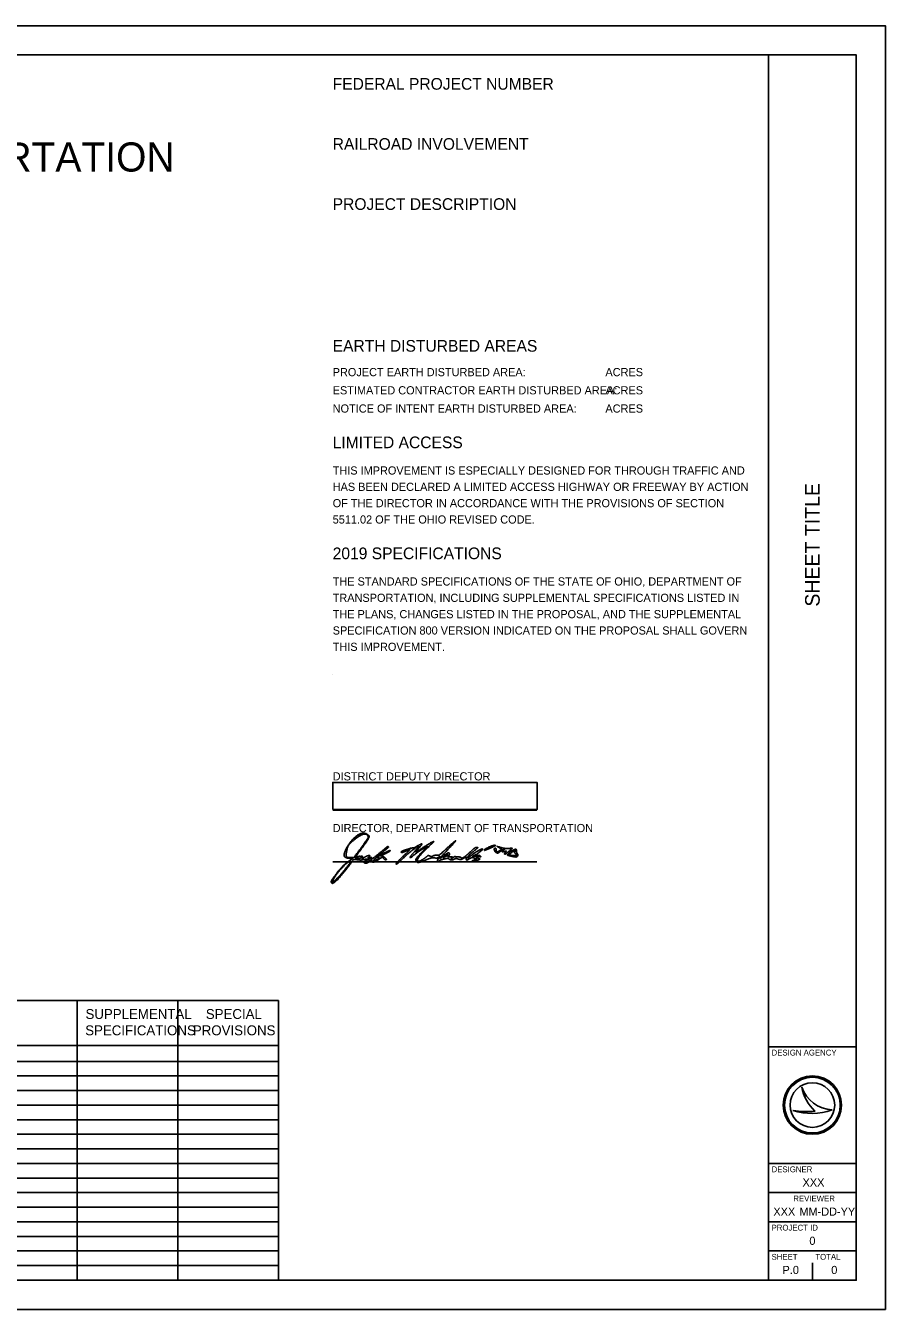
# Model space of a CAD drawing. Extents: x -15 to 405, y -40 to 87.
# Drawn here: x 71.42 to 86.16, y -40.29 to -18.29 of the extents above; entities that cross this region are included whole.
import ezdxf

# ---------------------------------------------------------------- set-up
doc = ezdxf.new("R2010")
doc.units = 0
for name, color, linetype in [('GM_X_Adjacent_County', 7, 'Continuous'), ('GM_X_County', 7, 'Continuous'), ('GM_X_Section', 7, 'Continuous'), ('GM_X_Township', 7, 'Continuous')]:
    doc.layers.add(name, color=color, linetype=linetype)

msp = doc.modelspace()

# ---------------------------------------------------------------- linework, layer by layer
at = {"layer": 'GM_X_Adjacent_County'}
for p, q in [((77.146, -32.413), (77.146, -32.413)), ((77.466, -32.544), (77.466, -32.544)), ((77.511, -32.502), (77.511, -32.502)), ((77.883, -32.531), (77.883, -32.531)), ((78.66, -32.5), (78.66, -32.5)), ((79.285, -32.413), (79.285, -32.413)), ((79.738, -32.52), (79.738, -32.52))]:
    msp.add_line(p, q, dxfattribs=at)
for points in [[(76.998, -32.58), (77.029, -32.558), (76.991, -32.558)], [(78.608, -32.52), (78.579, -32.546), (78.62, -32.526)], [(79.549, -32.423), (79.585, -32.401), (79.545, -32.379)], [(79.798, -32.507), (79.854, -32.506), (79.825, -32.484)], [(77.241, -32.599), (77.262, -32.567), (77.221, -32.577)]]:
    msp.add_lwpolyline(points, dxfattribs=at)
for points in [[(77.038, -32.251), (76.972, -32.308), (76.933, -32.372), (76.922, -32.443)], [(76.935, -32.362), (77.021, -32.211), (77.229, -32.095), (77.295, -32.161)], [(77.286, -32.17), (77.26, -32.128), (77.134, -32.169), (77.038, -32.251)], [(77.146, -32.413), (77.267, -32.249), (77.3, -32.193), (77.286, -32.17)], [(77.295, -32.223), (77.284, -32.246), (77.232, -32.322), (77.18, -32.391)], [(77.295, -32.161), (77.313, -32.18), (77.313, -32.185), (77.295, -32.223)], [(78.129, -32.35), (78.208, -32.304), (78.22, -32.317), (78.161, -32.384)], [(78.188, -32.403), (78.269, -32.347), (78.4, -32.269), (78.416, -32.269)], [(78.416, -32.269), (78.421, -32.269), (78.379, -32.312), (78.324, -32.364)], [(78.643, -32.383), (78.718, -32.314), (78.784, -32.257), (78.789, -32.257)], [(78.789, -32.257), (78.795, -32.257), (78.743, -32.317), (78.674, -32.391)], [(79.285, -32.413), (79.285, -32.401), (79.438, -32.331), (79.457, -32.334)], [(79.457, -32.334), (79.478, -32.338), (79.478, -32.338), (79.357, -32.393)], [(76.991, -32.558), (76.893, -32.556), (76.87, -32.475), (76.935, -32.362)], [(76.922, -32.443), (76.91, -32.517), (76.932, -32.544), (77, -32.544)], [(77, -32.544), (77.046, -32.544), (77.051, -32.54), (77.146, -32.413)], [(77.091, -32.545), (77.069, -32.546), (77.069, -32.547), (77.096, -32.558)], [(77.18, -32.391), (77.128, -32.461), (77.085, -32.521), (77.085, -32.526)], [(77.085, -32.526), (77.085, -32.531), (77.101, -32.531), (77.12, -32.527)], [(77.135, -32.531), (77.125, -32.538), (77.105, -32.545), (77.091, -32.545)], [(77.096, -32.558), (77.126, -32.57), (77.182, -32.545), (77.164, -32.528)], [(77.12, -32.527), (77.145, -32.521), (77.149, -32.522), (77.135, -32.531)], [(77.164, -32.528), (77.16, -32.523), (77.166, -32.519), (77.178, -32.519)], [(77.178, -32.519), (77.193, -32.519), (77.198, -32.526), (77.193, -32.538)], [(77.193, -32.538), (77.184, -32.561), (77.197, -32.562), (77.229, -32.54)], [(77.229, -32.54), (77.258, -32.52), (77.323, -32.503), (77.323, -32.515)], [(77.263, -32.619), (77.286, -32.619), (77.412, -32.531), (77.525, -32.435)], [(77.301, -32.539), (77.282, -32.553), (77.284, -32.554), (77.317, -32.549)], [(77.323, -32.515), (77.323, -32.519), (77.313, -32.53), (77.301, -32.539)], [(77.317, -32.549), (77.353, -32.543), (77.353, -32.544), (77.308, -32.569)], [(77.466, -32.544), (77.449, -32.538), (77.433, -32.543), (77.413, -32.561)], [(77.541, -32.449), (77.448, -32.523), (77.427, -32.544), (77.471, -32.521)], [(77.438, -32.58), (77.485, -32.557), (77.488, -32.552), (77.466, -32.544)], [(77.471, -32.521), (77.483, -32.514), (77.507, -32.512), (77.524, -32.516)], [(77.557, -32.557), (77.54, -32.533), (77.538, -32.534), (77.472, -32.576)], [(77.515, -32.507), (77.51, -32.507), (77.508, -32.505), (77.511, -32.502)], [(77.511, -32.502), (77.532, -32.485), (77.664, -32.419), (77.669, -32.424)], [(77.669, -32.424), (77.675, -32.43), (77.532, -32.507), (77.515, -32.507)], [(77.524, -32.516), (77.56, -32.525), (77.618, -32.582), (77.592, -32.582)], [(77.525, -32.435), (77.575, -32.392), (77.621, -32.357), (77.626, -32.357)], [(77.626, -32.357), (77.651, -32.357), (77.627, -32.382), (77.541, -32.449)], [(77.592, -32.582), (77.582, -32.582), (77.566, -32.571), (77.557, -32.557)], [(77.773, -32.656), (77.762, -32.656), (77.812, -32.6), (77.883, -32.531)], [(78.157, -32.35), (78.148, -32.34), (77.938, -32.507), (77.86, -32.587)], [(77.86, -32.448), (77.861, -32.437), (78.048, -32.374), (78.064, -32.379)], [(77.941, -32.432), (77.879, -32.459), (77.86, -32.462), (77.86, -32.448)], [(77.883, -32.531), (77.954, -32.463), (78.009, -32.407), (78.006, -32.407)], [(78.006, -32.407), (78.003, -32.407), (77.974, -32.418), (77.941, -32.432)], [(78.014, -32.544), (78.004, -32.544), (78.032, -32.503), (78.08, -32.45)], [(78.047, -32.526), (78.039, -32.536), (78.024, -32.544), (78.014, -32.544)], [(78.298, -32.351), (78.249, -32.378), (78.06, -32.511), (78.047, -32.526)], [(78.064, -32.379), (78.069, -32.381), (78.099, -32.368), (78.129, -32.35)], [(78.08, -32.45), (78.126, -32.399), (78.161, -32.354), (78.157, -32.35)], [(78.125, -32.615), (78.1, -32.59), (78.129, -32.54), (78.233, -32.429)], [(78.161, -32.384), (78.133, -32.416), (78.11, -32.446), (78.11, -32.45)], [(78.11, -32.45), (78.11, -32.455), (78.145, -32.434), (78.188, -32.403)], [(78.324, -32.364), (78.224, -32.458), (78.135, -32.566), (78.135, -32.593)], [(78.153, -32.607), (78.175, -32.607), (78.256, -32.562), (78.293, -32.529)], [(78.233, -32.429), (78.279, -32.38), (78.308, -32.345), (78.298, -32.351)], [(78.293, -32.529), (78.313, -32.511), (78.326, -32.509), (78.35, -32.518)], [(78.431, -32.55), (78.401, -32.547), (78.362, -32.553), (78.325, -32.568)], [(78.35, -32.518), (78.37, -32.526), (78.389, -32.525), (78.405, -32.516)], [(78.405, -32.516), (78.418, -32.508), (78.446, -32.504), (78.468, -32.505)], [(78.5, -32.536), (78.484, -32.55), (78.463, -32.555), (78.431, -32.55)], [(78.468, -32.505), (78.501, -32.508), (78.525, -32.492), (78.643, -32.383)], [(78.497, -32.607), (78.479, -32.607), (78.483, -32.574), (78.504, -32.557)], [(78.523, -32.529), (78.523, -32.521), (78.513, -32.525), (78.5, -32.536)], [(78.504, -32.557), (78.514, -32.548), (78.523, -32.536), (78.523, -32.529)], [(78.674, -32.391), (78.544, -32.528), (78.512, -32.576), (78.594, -32.508)], [(78.676, -32.567), (78.664, -32.556), (78.644, -32.557), (78.591, -32.57)], [(78.594, -32.508), (78.643, -32.468), (78.685, -32.458), (78.685, -32.486)], [(78.66, -32.5), (78.66, -32.487), (78.636, -32.496), (78.608, -32.52)], [(78.62, -32.526), (78.642, -32.515), (78.66, -32.504), (78.66, -32.5)], [(78.67, -32.517), (78.659, -32.529), (78.664, -32.532), (78.697, -32.532)], [(78.685, -32.486), (78.685, -32.495), (78.678, -32.509), (78.67, -32.517)], [(78.697, -32.532), (78.734, -32.532), (78.737, -32.534), (78.721, -32.553)], [(78.721, -32.553), (78.709, -32.568), (78.716, -32.567), (78.743, -32.547)], [(78.743, -32.547), (78.764, -32.532), (78.785, -32.523), (78.789, -32.527)], [(78.789, -32.527), (78.793, -32.531), (78.816, -32.534), (78.841, -32.534)], [(78.926, -32.558), (78.888, -32.577), (78.87, -32.579), (78.836, -32.57)], [(78.841, -32.534), (78.865, -32.534), (78.885, -32.54), (78.885, -32.546)], [(78.885, -32.546), (78.885, -32.569), (78.98, -32.507), (79.051, -32.439)], [(78.973, -32.559), (78.973, -32.536), (78.972, -32.536), (78.926, -32.558)], [(79.035, -32.562), (78.99, -32.588), (78.973, -32.587), (78.973, -32.559)], [(79.123, -32.417), (79.049, -32.478), (78.998, -32.531), (78.998, -32.548)], [(78.998, -32.548), (78.998, -32.556), (79.013, -32.548), (79.032, -32.53)], [(79.032, -32.53), (79.086, -32.482), (79.233, -32.392), (79.25, -32.397)], [(79.118, -32.554), (79.079, -32.544), (79.062, -32.545), (79.035, -32.562)], [(79.051, -32.439), (79.096, -32.395), (79.133, -32.37), (79.151, -32.37)], [(79.126, -32.5), (79.076, -32.515), (79.096, -32.529), (79.148, -32.515)], [(79.148, -32.573), (79.159, -32.569), (79.147, -32.561), (79.118, -32.554)], [(79.151, -32.37), (79.175, -32.371), (79.171, -32.377), (79.123, -32.417)], [(79.16, -32.483), (79.157, -32.488), (79.141, -32.495), (79.126, -32.5)], [(79.148, -32.515), (79.186, -32.505), (79.201, -32.506), (79.213, -32.518)], [(79.195, -32.525), (79.158, -32.516), (79.145, -32.539), (79.179, -32.552)], [(79.179, -32.552), (79.209, -32.564), (79.201, -32.579), (79.154, -32.595)], [(79.216, -32.439), (79.189, -32.459), (79.164, -32.479), (79.16, -32.483)], [(79.213, -32.518), (79.226, -32.531), (79.222, -32.532), (79.195, -32.525)], [(79.25, -32.397), (79.258, -32.4), (79.243, -32.419), (79.216, -32.439)], [(79.357, -32.393), (79.294, -32.421), (79.285, -32.423), (79.285, -32.413)], [(79.486, -32.458), (79.46, -32.443), (79.449, -32.382), (79.473, -32.382)], [(79.473, -32.382), (79.48, -32.382), (79.485, -32.396), (79.485, -32.413)], [(79.485, -32.413), (79.485, -32.45), (79.499, -32.452), (79.549, -32.423)], [(79.561, -32.439), (79.521, -32.466), (79.508, -32.469), (79.486, -32.458)], [(79.545, -32.379), (79.502, -32.354), (79.501, -32.354), (79.604, -32.381)], [(79.609, -32.428), (79.633, -32.398), (79.617, -32.402), (79.561, -32.439)], [(79.628, -32.44), (79.595, -32.448), (79.593, -32.447), (79.609, -32.428)], [(79.604, -32.381), (79.625, -32.386), (79.67, -32.389), (79.704, -32.387)], [(79.648, -32.45), (79.663, -32.433), (79.66, -32.431), (79.628, -32.44)], [(79.677, -32.459), (79.645, -32.489), (79.622, -32.482), (79.648, -32.45)], [(79.702, -32.472), (79.732, -32.438), (79.711, -32.427), (79.677, -32.459)], [(79.738, -32.52), (79.683, -32.507), (79.677, -32.499), (79.702, -32.472)], [(79.704, -32.387), (79.759, -32.384), (79.764, -32.385), (79.744, -32.4)], [(79.745, -32.462), (79.702, -32.493), (79.718, -32.507), (79.798, -32.507)], [(79.744, -32.4), (79.715, -32.422), (79.738, -32.438), (79.772, -32.42)], [(79.856, -32.512), (79.848, -32.533), (79.807, -32.536), (79.738, -32.52)], [(79.805, -32.439), (79.815, -32.413), (79.807, -32.416), (79.745, -32.462)], [(79.772, -32.42), (79.812, -32.399), (79.835, -32.404), (79.835, -32.436)], [(79.825, -32.484), (79.805, -32.469), (79.799, -32.455), (79.805, -32.439)], [(79.835, -32.436), (79.835, -32.452), (79.842, -32.471), (79.849, -32.479)], [(79.849, -32.479), (79.857, -32.486), (79.86, -32.502), (79.856, -32.512)], [(76.958, -32.688), (76.805, -32.89), (76.66, -33.019), (76.66, -32.952)], [(76.991, -32.609), (76.97, -32.588), (76.752, -32.814), (76.705, -32.904)], [(76.747, -32.822), (76.825, -32.721), (76.905, -32.644), (76.998, -32.58)], [(76.776, -32.885), (76.843, -32.816), (76.999, -32.616), (76.991, -32.609)], [(77.079, -32.579), (77.046, -32.576), (77.034, -32.587), (76.958, -32.688)], [(77.221, -32.577), (77.18, -32.587), (77.158, -32.587), (77.079, -32.579)], [(77.24, -32.639), (77.222, -32.632), (77.222, -32.629), (77.241, -32.599)], [(77.307, -32.62), (77.281, -32.635), (77.251, -32.644), (77.24, -32.639)], [(77.308, -32.569), (77.257, -32.597), (77.237, -32.619), (77.263, -32.619)], [(77.358, -32.606), (77.355, -32.597), (77.336, -32.602), (77.307, -32.62)], [(77.472, -32.576), (77.403, -32.62), (77.366, -32.63), (77.358, -32.606)], [(77.413, -32.561), (77.369, -32.601), (77.38, -32.61), (77.438, -32.58)], [(77.86, -32.587), (77.822, -32.625), (77.783, -32.656), (77.773, -32.656)], [(78.325, -32.568), (78.179, -32.625), (78.144, -32.634), (78.125, -32.615)], [(78.135, -32.593), (78.135, -32.601), (78.143, -32.607), (78.153, -32.607)], [(78.515, -32.597), (78.512, -32.602), (78.503, -32.607), (78.497, -32.607)], [(78.591, -32.57), (78.553, -32.579), (78.519, -32.591), (78.515, -32.597)], [(78.772, -32.57), (78.741, -32.586), (78.693, -32.585), (78.676, -32.567)], [(78.836, -32.57), (78.81, -32.562), (78.786, -32.562), (78.772, -32.57)], [(79.154, -32.595), (79.107, -32.61), (79.06, -32.604), (79.104, -32.588)], [(79.104, -32.588), (79.118, -32.584), (79.137, -32.577), (79.148, -32.573)], [(76.66, -32.952), (76.66, -32.942), (76.699, -32.884), (76.747, -32.822)], [(76.705, -32.904), (76.674, -32.965), (76.706, -32.956), (76.776, -32.885)]]:
    msp.add_open_spline(points, degree=2, dxfattribs=at)
at = {"layer": 'GM_X_County'}
for p, q in [((84.156, -39.787), (84.156, -18.787)), ((84.156, -35.787), (85.656, -35.787)), ((84.156, -37.787), (85.656, -37.787)), ((84.156, -38.287), (85.656, -38.287)), ((84.156, -38.787), (85.656, -38.787)), ((84.156, -39.287), (85.656, -39.287))]:
    msp.add_line(p, q, dxfattribs=at)
msp.add_lwpolyline([(53.656, -18.787), (85.656, -18.787), (85.656, -39.787), (53.656, -39.787)], close=True, dxfattribs=at)
at = {"layer": 'GM_X_Section'}
msp.add_lwpolyline([(52.156, -40.287), (86.156, -40.287), (86.156, -18.287), (52.156, -18.287)], close=True, dxfattribs=at)
at = {"layer": 'GM_X_Township'}
for p, q in [((76.684, -29.412), (76.684, -29.412)), ((76.684, -31.732), (80.184, -31.732)), ((76.684, -32.618), (80.184, -32.618)), ((62.306, -34.995), (75.756, -34.995)), ((72.306, -39.787), (72.306, -34.995)), ((74.031, -39.787), (74.031, -34.995)), ((75.756, -39.787), (75.756, -34.995)), ((62.306, -35.766), (75.756, -35.766)), ((62.306, -36.037), (75.756, -36.037)), ((62.306, -36.287), (75.756, -36.287)), ((84.723, -36.477), (84.723, -36.477)), ((62.306, -36.537), (75.756, -36.537)), ((62.306, -36.787), (75.756, -36.787)), ((84.573, -36.877), (84.573, -36.877)), ((84.906, -36.787), (84.906, -36.787)), ((85.243, -36.868), (85.243, -36.868)), ((62.306, -37.037), (75.756, -37.037)), ((62.306, -37.287), (75.756, -37.287)), ((62.306, -37.537), (75.756, -37.537)), ((62.306, -37.787), (75.756, -37.787)), ((62.306, -38.037), (75.756, -38.037)), ((62.306, -38.287), (75.756, -38.287)), ((62.306, -38.537), (75.756, -38.537)), ((62.306, -38.787), (75.756, -38.787)), ((62.306, -39.037), (75.756, -39.037)), ((62.306, -39.287), (75.756, -39.287)), ((62.306, -39.537), (75.756, -39.537)), ((84.906, -39.787), (84.906, -39.487)), ((84.531, -39.612), (84.531, -39.612))]:
    msp.add_line(p, q, dxfattribs=at)
msp.add_lwpolyline([(76.684, -31.722), (76.684, -31.257), (80.188, -31.257), (80.188, -31.722)], close=True, dxfattribs=at)
for radius in [0.5, 0.477, 0.477, 0.382]:
    msp.add_circle((84.906, -36.787), radius, dxfattribs=at)
for centre, radius, start, end in [((85.272, -36.289), 0.58, 198.9257, 198.9319), ((85.502, -36.317), 0.796, 191.6379, 191.6421), ((85.272, -36.289), 0.58, 198.9319, 267.1657), ((85.502, -36.317), 0.796, 191.6421, 226.0947), ((84.895, -35.917), 1.013, 251.4576, 290.0832), ((84.804, -35.632), 1.266, 259.4964, 259.4995), ((84.895, -35.917), 1.013, 251.4527, 251.4576), ((84.804, -35.632), 1.266, 259.4995, 276.6672)]:
    msp.add_arc(centre, radius, start, end, dxfattribs=at)

# ---------------------------------------------------------------- texts
at = {"layer": 'GM_X_Adjacent_County'}
for s, height, p in [('FEDERAL PROJECT NUMBER', 0.2, (76.684, -19.384)), ('RAILROAD INVOLVEMENT', 0.2, (76.684, -20.414)), ('DEPARTMENT OF TRANSPORTATION', 0.5, (61.902, -20.787)), ('PROJECT DESCRIPTION', 0.2, (76.684, -21.444)), ('EARTH DISTURBED AREAS', 0.2, (76.684, -23.874)), ('PROJECT EARTH DISTURBED AREA:', 0.14, (76.684, -24.294)), ('     ACRES', 0.14, (81.098, -24.294)), ('ESTIMATED CONTRACTOR EARTH DISTURBED AREA:', 0.14, (76.684, -24.606)), ('     ACRES', 0.14, (81.098, -24.606)), ('NOTICE OF INTENT EARTH DISTURBED AREA:', 0.14, (76.684, -24.918)), ('     ACRES', 0.14, (81.098, -24.918)), ('LIMITED ACCESS', 0.2, (76.684, -25.528)), ('THIS IMPROVEMENT IS ESPECIALLY DESIGNED FOR THROUGH TRAFFIC AND', 0.14, (76.684, -25.98)), ('HAS BEEN DECLARED A LIMITED ACCESS HIGHWAY OR FREEWAY BY ACTION', 0.14, (76.684, -26.26)), ('OF THE DIRECTOR IN ACCORDANCE WITH THE PROVISIONS OF SECTION', 0.14, (76.684, -26.54)), ('5511.02 OF THE OHIO REVISED CODE.', 0.14, (76.684, -26.82)), ('2019 SPECIFICATIONS', 0.2, (76.684, -27.43)), ('THE STANDARD SPECIFICATIONS OF THE STATE OF OHIO, DEPARTMENT OF', 0.14, (76.684, -27.882)), ('TRANSPORTATION, INCLUDING SUPPLEMENTAL SPECIFICATIONS LISTED IN', 0.14, (76.684, -28.162)), ('THE PLANS, CHANGES LISTED IN THE PROPOSAL, AND THE SUPPLEMENTAL', 0.14, (76.684, -28.442)), ('SPECIFICATION 800 VERSION INDICATED ON THE PROPOSAL SHALL GOVERN', 0.14, (76.684, -28.722)), ('THIS IMPROVEMENT.', 0.14, (76.684, -29.002)), ('DISTRICT DEPUTY DIRECTOR', 0.14, (76.684, -31.222)), ('DIRECTOR, DEPARTMENT OF TRANSPORTATION', 0.14, (76.684, -32.108)), ('SUPPLEMENTAL', 0.17, (72.448, -35.31)), ('SPECIAL', 0.17, (74.51, -35.31)), ('SPECIFICATIONS', 0.17, (72.443, -35.59)), ('PROVISIONS', 0.17, (74.288, -35.59))]:
    msp.add_text(s, height=height, dxfattribs=at).set_placement(p)
at = {"layer": 'GM_X_Township'}
msp.add_text('SHEET TITLE', height=0.25, rotation=90, dxfattribs=at).set_placement((85.031, -28.243))
for s, height, p in [('DESIGN AGENCY', 0.1, (84.206, -35.937)), ('DESIGNER', 0.1, (84.206, -37.937)), ('XXX', 0.14, (84.737, -38.182)), ('REVIEWER', 0.1, (84.578, -38.437)), ('XXX', 0.14, (84.237, -38.682)), ('MM-DD-YY', 0.14, (84.683, -38.682)), ('PROJECT ID', 0.1, (84.206, -38.937)), ('0', 0.14, (84.854, -39.182)), ('SHEET', 0.1, (84.206, -39.437)), ('TOTAL', 0.1, (84.956, -39.437)), ('P.0', 0.14, (84.394, -39.682)), ('0', 0.14, (85.229, -39.682))]:
    msp.add_text(s, height=height, dxfattribs=at).set_placement(p)

doc.saveas('drawing.dxf')
